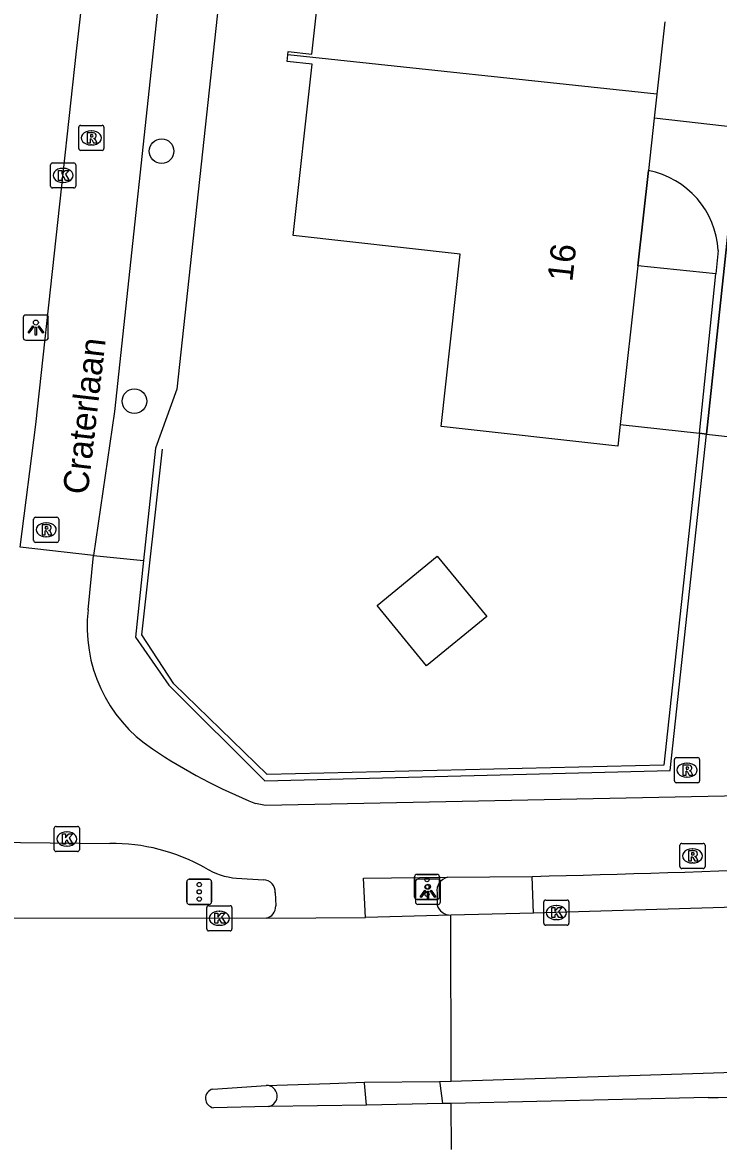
# Model space of a CAD drawing. Extents: x 162398 to 163643, y 386453 to 387397.
# Drawn here: x 162646 to 162673.7, y 386452.93 to 386497.76 of the extents above; entities that cross this region are included whole.
import ezdxf

# ---------------------------------------------------------------- set-up
doc = ezdxf.new("R2010")
doc.units = 0
for name, color, linetype in [('IMGEO_Boom', 7, 'Continuous'), ('IMGEO_Fietspad_gesloten', 7, 'Continuous'), ('IMGEO_Fietspad_open', 7, 'Continuous'), ('IMGEO_Kolk', 7, 'Continuous'), ('IMGEO_Lichtpunt', 7, 'Continuous'), ('IMGEO_Muur', 7, 'Continuous'), ('IMGEO_Openbare_ruimte_label', 7, 'Continuous'), ('IMGEO_Pand', 7, 'Continuous'), ('IMGEO_Pand_nummerreeks', 7, 'Continuous'), ('IMGEO_Pand_overbouw', 7, 'Continuous'), ('IMGEO_Rijbaan_lokaal_open', 7, 'Continuous'), ('IMGEO_Rijbaan_regionaal_gesloten', 7, 'Continuous'), ('IMGEO_Rioolput', 7, 'Continuous'), ('IMGEO_Verkeerseiland_gesloten', 7, 'Continuous'), ('IMGEO_Verkeersregelinstallatiepaal', 7, 'Continuous'), ('IMGEO_Voetpad_open', 7, 'Continuous')]:
    doc.layers.add(name, color=color, linetype=linetype)

msp = doc.modelspace()

# ---------------------------------------------------------------- linework, layer by layer
at = {"layer": 'IMGEO_Boom'}
for centre in [(162651.534, 386492.646), (162650.454, 386482.699)]:
    msp.add_circle(centre, 0.489, dxfattribs=at)
at = {"layer": 'IMGEO_Fietspad_gesloten'}
for points in [[(162648.825, 386476.553), (162645.908, 386476.892)], [(162648.608, 386474.401), (162648.825, 386476.553)], [(162674.593, 386466.997), (162655.671, 386466.609), (162655.276, 386466.693)], [(162624.53, 386465.372), (162649.473, 386465.101)], [(162654.519, 386463.716), (162655.594, 386463.659)], [(162659.652, 386462.15), (162659.567, 386463.727), (162662.92, 386463.76)], [(162662.92, 386463.76), (162666.294, 386463.792)], [(162656.056, 386463.144), (162656.079, 386462.619)], [(162659.696, 386454.688), (162659.613, 386455.559), (162659.609, 386455.599)]]:
    msp.add_lwpolyline(points, dxfattribs=at)
for centre, radius, start, end in [((162654.434, 386473.733), 5.864, 173.4629, 236.1556), ((162663.327, 386486.908), 21.759, 236.0268, 248.2838), ((162649.564, 386457.588), 7.514, 60.4782, 90.6972), ((162642.685, 387395.376), 931.884, 271.451743, 272.779253), ((162654.827, 386466.772), 3.071, 239.4829, 264.2523), ((162655.585, 386463.186), 0.473, 354.8766, 88.9132), ((162655.591, 386462.603), 0.488, 282.1807, 1.8444), ((162655.711, 386455.05), 0.425, 280.0065, 90.9703)]:
    msp.add_arc(centre, radius, start, end, dxfattribs=at)
at = {"layer": 'IMGEO_Fietspad_open'}
for points in [[(162655.899, 386540.406), (162651.56, 386500), (162649.657, 386482.292), (162648.825, 386476.553)], [(162645.908, 386476.892), (162646.532, 386481.777), (162648.149, 386496.622), (162648.531, 386500), (162651.092, 386522.672), (162652.314, 386534.776)]]:
    msp.add_lwpolyline(points, dxfattribs=at)
at = {"layer": 'IMGEO_Kolk'}
for p, q in [((162647.116, 386491.255), (162647.116, 386492.107)), ((162647.191, 386492.181), (162648.043, 386492.181)), ((162647.604, 386491.961), (162647.629, 386491.961)), ((162648.117, 386492.107), (162648.117, 386491.255)), ((162647.627, 386491.401), (162647.602, 386491.401)), ((162648.043, 386491.181), (162647.191, 386491.181)), ((162647.263, 386464.854), (162647.263, 386465.706)), ((162647.338, 386465.78), (162648.19, 386465.78)), ((162647.751, 386465.56), (162647.776, 386465.56)), ((162648.264, 386465.706), (162648.264, 386464.854)), ((162647.774, 386465), (162647.749, 386465)), ((162648.19, 386464.78), (162647.338, 386464.78)), ((162666.75, 386461.925), (162666.75, 386462.777)), ((162666.825, 386462.851), (162667.677, 386462.851)), ((162667.751, 386462.777), (162667.751, 386461.925)), ((162653.334, 386461.699), (162653.334, 386462.551)), ((162653.409, 386462.625), (162654.261, 386462.625)), ((162653.822, 386462.405), (162653.847, 386462.405)), ((162654.335, 386462.551), (162654.335, 386461.699)), ((162667.238, 386462.631), (162667.263, 386462.631)), ((162653.845, 386461.845), (162653.82, 386461.845)), ((162667.677, 386461.851), (162666.825, 386461.851)), ((162667.261, 386462.071), (162667.236, 386462.071)), ((162654.261, 386461.625), (162653.409, 386461.625))]:
    msp.add_line(p, q, dxfattribs=at)
for points in [[(162647.116, 386491.255), (162647.116, 386492.107)], [(162647.191, 386492.181), (162648.043, 386492.181)], [(162647.437, 386491.881), (162647.56, 386491.881), (162647.56, 386491.73), (162647.69, 386491.881), (162647.854, 386491.881), (162647.708, 386491.73), (162647.861, 386491.481), (162647.709, 386491.481), (162647.624, 386491.645), (162647.56, 386491.578), (162647.56, 386491.481), (162647.437, 386491.481), (162647.437, 386491.881)], [(162648.117, 386492.107), (162648.117, 386491.255)], [(162648.043, 386491.181), (162647.191, 386491.181)], [(162647.263, 386464.854), (162647.263, 386465.706)], [(162647.338, 386465.78), (162648.19, 386465.78)], [(162647.584, 386465.48), (162647.707, 386465.48), (162647.707, 386465.329), (162647.837, 386465.48), (162648.001, 386465.48), (162647.855, 386465.329), (162648.008, 386465.08), (162647.856, 386465.08), (162647.771, 386465.244), (162647.707, 386465.177), (162647.707, 386465.08), (162647.584, 386465.08), (162647.584, 386465.48)], [(162648.264, 386465.706), (162648.264, 386464.854)], [(162648.19, 386464.78), (162647.338, 386464.78)], [(162666.75, 386461.925), (162666.75, 386462.777)], [(162666.825, 386462.851), (162667.677, 386462.851)], [(162667.751, 386462.777), (162667.751, 386461.925)], [(162653.334, 386461.699), (162653.334, 386462.551)], [(162653.409, 386462.625), (162654.261, 386462.625)], [(162653.655, 386462.325), (162653.778, 386462.325), (162653.778, 386462.174), (162653.908, 386462.325), (162654.072, 386462.325), (162653.926, 386462.174), (162654.079, 386461.925), (162653.927, 386461.925), (162653.842, 386462.089), (162653.778, 386462.022), (162653.778, 386461.925), (162653.655, 386461.925), (162653.655, 386462.325)], [(162654.335, 386462.551), (162654.335, 386461.699)], [(162667.071, 386462.551), (162667.194, 386462.551), (162667.194, 386462.4), (162667.324, 386462.551), (162667.488, 386462.551), (162667.342, 386462.4), (162667.495, 386462.151), (162667.343, 386462.151), (162667.258, 386462.315), (162667.194, 386462.248), (162667.194, 386462.151), (162667.071, 386462.151), (162667.071, 386462.551)], [(162667.677, 386461.851), (162666.825, 386461.851)], [(162654.261, 386461.625), (162653.409, 386461.625)]]:
    msp.add_lwpolyline(points, dxfattribs=at)
for centre, start, end in [((162647.193, 386492.105), 91.552, 178.448), ((162647.193, 386492.105), 91.552, 178.448), ((162648.041, 386492.105), 1.552, 88.448), ((162648.041, 386492.105), 1.552, 88.448), ((162647.193, 386491.257), 181.552, 268.448), ((162647.193, 386491.257), 181.552, 268.448), ((162648.041, 386491.257), 271.552, 358.448), ((162648.041, 386491.257), 271.552, 358.448), ((162647.34, 386465.704), 91.552, 178.448), ((162647.34, 386465.704), 91.552, 178.448), ((162648.188, 386465.704), 1.552, 88.448), ((162648.188, 386465.704), 1.552, 88.448), ((162647.34, 386464.856), 181.552, 268.448), ((162647.34, 386464.856), 181.552, 268.448), ((162648.188, 386464.856), 271.552, 358.448), ((162648.188, 386464.856), 271.552, 358.448), ((162666.827, 386462.775), 91.552, 178.448), ((162666.827, 386462.775), 91.552, 178.448), ((162667.675, 386462.775), 1.552, 88.448), ((162667.675, 386462.775), 1.552, 88.448), ((162653.411, 386462.549), 91.552, 178.448), ((162653.411, 386462.549), 91.552, 178.448), ((162654.259, 386462.549), 1.552, 88.448), ((162654.259, 386462.549), 1.552, 88.448), ((162666.827, 386461.927), 181.552, 268.448), ((162666.827, 386461.927), 181.552, 268.448), ((162667.675, 386461.927), 271.552, 358.448), ((162667.675, 386461.927), 271.552, 358.448), ((162653.411, 386461.701), 181.552, 268.448), ((162653.411, 386461.701), 181.552, 268.448), ((162654.259, 386461.701), 271.552, 358.448), ((162654.259, 386461.701), 271.552, 358.448)]:
    msp.add_arc(centre, 0.0765, start, end, dxfattribs=at)
for centre, major_axis, ratio, start_param, end_param in [((162647.603, 386491.681), (-0.387, 0.002), 0.722429, 4.712389, 7.853982), ((162647.628, 386491.681), (-0.39, 0.002), 0.717154, 1.570796, 4.712389), ((162647.75, 386465.28), (-0.387, 0.002), 0.722429, 4.712389, 7.853982), ((162647.775, 386465.28), (-0.39, 0.002), 0.717154, 1.570796, 4.712389), ((162653.821, 386462.125), (-0.387, 0.002), 0.722429, 4.712389, 7.853982), ((162653.846, 386462.125), (-0.39, 0.002), 0.717154, 1.570796, 4.712389), ((162667.237, 386462.351), (-0.387, 0.002), 0.722429, 4.712389, 7.853982), ((162667.262, 386462.351), (-0.39, 0.002), 0.717154, 1.570796, 4.712389)]:
    msp.add_ellipse(centre, major_axis=major_axis, ratio=ratio, start_param=start_param, end_param=end_param, dxfattribs=at)
at = {"layer": 'IMGEO_Lichtpunt'}
for p, q in [((162646.03, 386486.031), (162646.03, 386485.224)), ((162646.03, 386486.031), (162646.03, 386485.224)), ((162646.932, 386486.126), (162646.124, 386486.126)), ((162646.932, 386486.126), (162646.124, 386486.126)), ((162647.026, 386485.224), (162647.026, 386486.031)), ((162647.026, 386485.224), (162647.026, 386486.031)), ((162646.124, 386485.13), (162646.932, 386485.13)), ((162646.124, 386485.13), (162646.932, 386485.13)), ((162662.544, 386463.676), (162661.736, 386463.676)), ((162662.544, 386463.676), (162661.736, 386463.676)), ((162661.642, 386463.581), (162661.642, 386462.774)), ((162661.642, 386463.581), (162661.642, 386462.774)), ((162662.638, 386462.774), (162662.638, 386463.581)), ((162662.638, 386462.774), (162662.638, 386463.581)), ((162661.736, 386462.68), (162662.544, 386462.68)), ((162661.736, 386462.68), (162662.544, 386462.68))]:
    msp.add_line(p, q, dxfattribs=at)
for points in [[(162646.404, 386485.695), (162646.443, 386485.667), (162646.255, 386485.405), (162646.217, 386485.432), (162646.404, 386485.695)], [(162646.506, 386485.647), (162646.553, 386485.647), (162646.553, 386485.325), (162646.506, 386485.325), (162646.506, 386485.647)], [(162646.616, 386485.667), (162646.654, 386485.694), (162646.841, 386485.432), (162646.802, 386485.404), (162646.616, 386485.667)], [(162662.016, 386463.245), (162662.055, 386463.217), (162661.867, 386462.955), (162661.829, 386462.982), (162662.016, 386463.245)], [(162662.118, 386463.197), (162662.165, 386463.197), (162662.165, 386462.875), (162662.118, 386462.875), (162662.118, 386463.197)], [(162662.228, 386463.217), (162662.266, 386463.244), (162662.453, 386462.982), (162662.414, 386462.954), (162662.228, 386463.217)]]:
    msp.add_lwpolyline(points, dxfattribs=at)
for centre in [(162646.529, 386485.829), (162662.141, 386463.379)]:
    msp.add_circle(centre, 0.0994, dxfattribs=at)
for centre, start, end in [((162646.124, 386486.031), 90, 180), ((162646.124, 386486.031), 90, 180), ((162646.932, 386486.031), 0, 90), ((162646.932, 386486.031), 0, 90), ((162646.124, 386485.224), 180, 270), ((162646.124, 386485.224), 180, 270), ((162646.932, 386485.224), 270, 0), ((162646.932, 386485.224), 270, 360), ((162661.736, 386463.581), 90, 180), ((162661.736, 386463.581), 90, 180), ((162662.544, 386463.581), 0, 90), ((162662.544, 386463.581), 0, 90), ((162661.736, 386462.774), 180, 270), ((162661.736, 386462.774), 180, 270), ((162662.544, 386462.774), 270, 0), ((162662.544, 386462.774), 270, 360)]:
    msp.add_arc(centre, 0.0946, start, end, dxfattribs=at)
at = {"layer": 'IMGEO_Muur'}
for points in [[(162672.948, 386481.421), (162672.85, 386480.517)], [(162672.85, 386480.517), (162671.524, 386468.223), (162655.736, 386467.848), (162652.022, 386471.451), (162650.749, 386473.407), (162651.57, 386480.789)]]:
    msp.add_lwpolyline(points, dxfattribs=at)
at = {"layer": 'IMGEO_Pand'}
for points in [[(162656.562, 386496.484), (162656.576, 386496.61), (162657.511, 386496.506), (162657.899, 386500), (162658.285, 386503.471), (162664.964, 386502.729), (162665.724, 386509.568)], [(162671.571, 386497.786), (162671.251, 386494.908)], [(162670.493, 386488.084), (162669.791, 386481.774), (162669.695, 386480.909), (162662.664, 386481.69), (162663.427, 386488.55), (162656.767, 386489.29), (162657.524, 386496.103), (162656.532, 386496.213), (162656.562, 386496.484)], [(162671.251, 386494.908), (162656.562, 386496.484)], [(162671.251, 386494.908), (162671.145, 386493.953), (162670.914, 386491.872)], [(162670.493, 386488.084), (162670.914, 386491.872)], [(162662.512, 386476.528), (162664.477, 386474.131), (162662.08, 386472.165), (162660.114, 386474.563), (162662.512, 386476.528)]]:
    msp.add_lwpolyline(points, dxfattribs=at)
at = {"layer": 'IMGEO_Pand_overbouw'}
for points in [[(162674.534, 386493.571), (162671.145, 386493.953), (162670.914, 386491.872), (162670.493, 386488.084), (162669.791, 386481.774), (162672.948, 386481.421), (162673.225, 386481.39)], [(162674.534, 386493.571), (162673.225, 386481.39), (162676.718, 386481), (162678.111, 386493.167)]]:
    msp.add_lwpolyline(points, close=True, dxfattribs=at)
at = {"layer": 'IMGEO_Rijbaan_lokaal_open'}
for points in [[(162673.689, 386488.692), (162673.598, 386487.762)], [(162673.225, 386481.39), (162672.948, 386481.421), (162673.598, 386487.762)], [(162673.225, 386481.39), (162676.718, 386481)]]:
    msp.add_lwpolyline(points, dxfattribs=at)
msp.add_arc((162670.277, 386488.515), 3.417, 2.9638, 79.2548, dxfattribs=at)
at = {"layer": 'IMGEO_Rijbaan_regionaal_gesloten'}
for points in [[(162738.894, 386466.632), (162707.241, 386464.248), (162696.541, 386463.625), (162677.057, 386462.649), (162666.342, 386462.323)], [(162666.342, 386462.323), (162663.044, 386462.248)], [(162655.694, 386462.126), (162624.533, 386462.102)], [(162655.694, 386462.126), (162659.652, 386462.15)], [(162663.044, 386462.248), (162659.652, 386462.15)], [(162663.064, 386455.639), (162663.044, 386462.248)], [(162663.064, 386455.639), (162683.946, 386456.306), (162698.037, 386457.061), (162718.633, 386458.415)], [(162655.704, 386455.475), (162658.249, 386455.556), (162659.609, 386455.599)], [(162659.609, 386455.599), (162662.604, 386455.624)], [(162662.604, 386455.624), (162663.064, 386455.639)], [(162653.577, 386455.329), (162655.704, 386455.475)], [(162655.785, 386454.632), (162653.602, 386454.587)], [(162659.696, 386454.688), (162655.785, 386454.632)], [(162662.716, 386454.749), (162659.696, 386454.688)], [(162663.067, 386454.757), (162662.716, 386454.749)], [(162673.297, 386454.988), (162663.067, 386454.757)], [(162663.073, 386452.927), (162663.067, 386454.757)]]:
    msp.add_lwpolyline(points, dxfattribs=at)
for centre, radius, start, end in [((162653.661, 386454.96), 0.378, 102.8084, 261.0511), ((162664.034, 386819.844), 364.974, 271.45438, 273.40835)]:
    msp.add_arc(centre, radius, start, end, dxfattribs=at)
at = {"layer": 'IMGEO_Rioolput'}
for p, q in [((162648.313, 386493.674), (162649.165, 386493.674)), ((162648.238, 386492.748), (162648.238, 386493.6)), ((162648.726, 386493.454), (162648.751, 386493.454)), ((162649.239, 386493.6), (162649.239, 386492.748)), ((162648.749, 386492.894), (162648.724, 386492.894)), ((162649.165, 386492.674), (162648.313, 386492.674)), ((162646.442, 386477.155), (162646.442, 386478.007)), ((162646.517, 386478.081), (162647.369, 386478.081)), ((162647.443, 386478.007), (162647.443, 386477.155)), ((162646.93, 386477.861), (162646.955, 386477.861)), ((162647.369, 386477.081), (162646.517, 386477.081)), ((162646.953, 386477.301), (162646.928, 386477.301)), ((162671.951, 386467.593), (162671.951, 386468.445)), ((162672.026, 386468.519), (162672.878, 386468.519)), ((162672.439, 386468.299), (162672.464, 386468.299)), ((162672.952, 386468.445), (162672.952, 386467.593)), ((162672.462, 386467.739), (162672.437, 386467.739)), ((162672.878, 386467.519), (162672.026, 386467.519)), ((162672.169, 386464.18), (162672.169, 386465.032)), ((162672.244, 386465.106), (162673.096, 386465.106)), ((162673.17, 386465.032), (162673.17, 386464.18)), ((162672.657, 386464.886), (162672.682, 386464.886)), ((162673.096, 386464.106), (162672.244, 386464.106)), ((162672.68, 386464.326), (162672.655, 386464.326))]:
    msp.add_line(p, q, dxfattribs=at)
for points in [[(162648.313, 386493.674), (162649.165, 386493.674)], [(162648.238, 386492.748), (162648.238, 386493.6)], [(162648.827, 386493.372), (162648.575, 386493.374), (162648.575, 386492.974)], [(162648.753, 386493.293), (162648.699, 386493.293), (162648.699, 386493.212)], [(162648.699, 386493.212), (162648.751, 386493.212)], [(162649.239, 386493.6), (162649.239, 386492.748)], [(162648.575, 386492.974), (162648.699, 386492.974), (162648.699, 386493.136), (162648.71, 386493.136)], [(162648.757, 386493.107), (162648.828, 386492.974), (162648.968, 386492.974), (162648.903, 386493.1)], [(162649.165, 386492.674), (162648.313, 386492.674)], [(162646.442, 386477.155), (162646.442, 386478.007)], [(162646.517, 386478.081), (162647.369, 386478.081)], [(162647.443, 386478.007), (162647.443, 386477.155)], [(162647.031, 386477.779), (162646.779, 386477.781), (162646.779, 386477.381)], [(162646.779, 386477.381), (162646.903, 386477.381), (162646.903, 386477.543), (162646.914, 386477.543)], [(162646.957, 386477.7), (162646.903, 386477.7), (162646.903, 386477.619)], [(162646.903, 386477.619), (162646.955, 386477.619)], [(162646.961, 386477.514), (162647.032, 386477.381), (162647.172, 386477.381), (162647.107, 386477.507)], [(162647.369, 386477.081), (162646.517, 386477.081)], [(162671.951, 386467.593), (162671.951, 386468.445)], [(162672.026, 386468.519), (162672.878, 386468.519)], [(162672.54, 386468.217), (162672.288, 386468.219), (162672.288, 386467.819)], [(162672.466, 386468.138), (162672.412, 386468.138), (162672.412, 386468.057)], [(162672.952, 386468.445), (162672.952, 386467.593)], [(162672.288, 386467.819), (162672.412, 386467.819), (162672.412, 386467.981), (162672.423, 386467.981)], [(162672.412, 386468.057), (162672.464, 386468.057)], [(162672.47, 386467.952), (162672.541, 386467.819), (162672.681, 386467.819), (162672.616, 386467.945)], [(162672.878, 386467.519), (162672.026, 386467.519)], [(162672.169, 386464.18), (162672.169, 386465.032)], [(162672.244, 386465.106), (162673.096, 386465.106)], [(162673.17, 386465.032), (162673.17, 386464.18)], [(162672.758, 386464.804), (162672.506, 386464.806), (162672.506, 386464.406)], [(162672.506, 386464.406), (162672.63, 386464.406), (162672.63, 386464.568), (162672.641, 386464.568)], [(162672.684, 386464.725), (162672.63, 386464.725), (162672.63, 386464.644)], [(162672.63, 386464.644), (162672.682, 386464.644)], [(162672.688, 386464.539), (162672.759, 386464.406), (162672.899, 386464.406), (162672.834, 386464.532)], [(162673.096, 386464.106), (162672.244, 386464.106)]]:
    msp.add_lwpolyline(points, dxfattribs=at)
for centre, radius, start, end in [((162648.315, 386493.598), 0.0765, 91.552, 178.448), ((162648.315, 386493.598), 0.0765, 91.552, 178.448), ((162649.163, 386493.598), 0.0765, 1.552, 88.448), ((162649.163, 386493.598), 0.0765, 1.552, 88.448), ((162648.735, 386493.401), 0.19, 274.7715, 282.9687), ((162648.759, 386493.197), 0.0964, 77.0061, 93.1865), ((162648.773, 386493.254), 0.0378, 276.6634, 79.6772), ((162648.826, 386493.262), 0.109, 350.3612, 89.416), ((162648.824, 386493.262), 0.112, 277.5842, 350.9817), ((162648.315, 386492.75), 0.0765, 181.552, 268.448), ((162648.315, 386492.75), 0.0765, 181.552, 268.448), ((162648.709, 386493.083), 0.0533, 26.0293, 88.6989), ((162648.808, 386493.047), 0.108, 29.5134, 73.7905), ((162649.163, 386492.75), 0.0765, 271.552, 358.448), ((162649.163, 386492.75), 0.0765, 271.552, 358.448), ((162646.519, 386478.005), 0.0765, 91.552, 178.448), ((162646.519, 386478.005), 0.0765, 91.552, 178.448), ((162647.367, 386478.005), 0.0765, 1.552, 88.448), ((162647.367, 386478.005), 0.0765, 1.552, 88.448), ((162646.913, 386477.49), 0.0533, 26.0293, 88.6989), ((162646.939, 386477.808), 0.19, 274.7715, 282.9687), ((162646.963, 386477.604), 0.0964, 77.0061, 93.1865), ((162646.977, 386477.661), 0.0378, 276.6634, 79.6772), ((162647.03, 386477.669), 0.109, 350.3612, 89.416), ((162647.028, 386477.669), 0.112, 277.5842, 350.9817), ((162647.012, 386477.454), 0.108, 29.5134, 73.7905), ((162646.519, 386477.157), 0.0765, 181.552, 268.448), ((162646.519, 386477.157), 0.0765, 181.552, 268.448), ((162647.367, 386477.157), 0.0765, 271.552, 358.448), ((162647.367, 386477.157), 0.0765, 271.552, 358.448), ((162672.028, 386468.443), 0.0765, 91.552, 178.448), ((162672.028, 386468.443), 0.0765, 91.552, 178.448), ((162672.472, 386468.042), 0.0964, 77.0061, 93.1865), ((162672.486, 386468.099), 0.0378, 276.6634, 79.6772), ((162672.539, 386468.107), 0.109, 350.3612, 89.416), ((162672.537, 386468.107), 0.112, 277.5842, 350.9817), ((162672.876, 386468.443), 0.0765, 1.552, 88.448), ((162672.876, 386468.443), 0.0765, 1.552, 88.448), ((162672.422, 386467.928), 0.0533, 26.0293, 88.6989), ((162672.448, 386468.246), 0.19, 274.7715, 282.9687), ((162672.521, 386467.892), 0.108, 29.5134, 73.7905), ((162672.028, 386467.595), 0.0765, 181.552, 268.448), ((162672.028, 386467.595), 0.0765, 181.552, 268.448), ((162672.876, 386467.595), 0.0765, 271.552, 358.448), ((162672.876, 386467.595), 0.0765, 271.552, 358.448), ((162672.246, 386465.03), 0.0765, 91.552, 178.448), ((162672.246, 386465.03), 0.0765, 91.552, 178.448), ((162673.094, 386465.03), 0.0765, 1.552, 88.448), ((162673.094, 386465.03), 0.0765, 1.552, 88.448), ((162672.64, 386464.515), 0.0533, 26.0293, 88.6989), ((162672.666, 386464.833), 0.19, 274.7715, 282.9687), ((162672.69, 386464.629), 0.0964, 77.0061, 93.1865), ((162672.704, 386464.686), 0.0378, 276.6634, 79.6772), ((162672.757, 386464.694), 0.109, 350.3612, 89.416), ((162672.755, 386464.694), 0.112, 277.5842, 350.9817), ((162672.739, 386464.479), 0.108, 29.5134, 73.7905), ((162672.246, 386464.182), 0.0765, 181.552, 268.448), ((162672.246, 386464.182), 0.0765, 181.552, 268.448), ((162673.094, 386464.182), 0.0765, 271.552, 358.448), ((162673.094, 386464.182), 0.0765, 271.552, 358.448)]:
    msp.add_arc(centre, radius, start, end, dxfattribs=at)
for centre, major_axis, ratio, start_param, end_param in [((162648.725, 386493.174), (-0.387, 0.002), 0.722429, 4.712389, 7.853982), ((162648.75, 386493.174), (-0.39, 0.002), 0.717154, 1.570796, 4.712389), ((162646.929, 386477.581), (-0.387, 0.002), 0.722429, 4.712389, 7.853982), ((162646.954, 386477.581), (-0.39, 0.002), 0.717154, 1.570796, 4.712389), ((162672.438, 386468.019), (-0.387, 0.002), 0.722429, 4.712389, 7.853982), ((162672.463, 386468.019), (-0.39, 0.002), 0.717154, 1.570796, 4.712389), ((162672.656, 386464.606), (-0.387, 0.002), 0.722429, 4.712389, 7.853982), ((162672.681, 386464.606), (-0.39, 0.002), 0.717154, 1.570796, 4.712389)]:
    msp.add_ellipse(centre, major_axis=major_axis, ratio=ratio, start_param=start_param, end_param=end_param, dxfattribs=at)
at = {"layer": 'IMGEO_Verkeerseiland_gesloten'}
msp.add_lwpolyline([(162666.342, 386462.323), (162666.294, 386463.792)], dxfattribs=at)
at = {"layer": 'IMGEO_Verkeersregelinstallatiepaal'}
for p, q in [((162652.637, 386463.677), (162653.427, 386463.677)), ((162653.427, 386463.677), (162652.637, 386463.677)), ((162661.605, 386462.971), (162661.605, 386463.771)), ((162661.605, 386463.771), (162661.605, 386462.971)), ((162661.705, 386463.871), (162662.495, 386463.871)), ((162662.495, 386463.871), (162661.705, 386463.871)), ((162662.595, 386463.771), (162662.595, 386462.971)), ((162662.595, 386462.971), (162662.595, 386463.771)), ((162652.537, 386462.777), (162652.537, 386463.577)), ((162652.537, 386463.577), (162652.537, 386462.777)), ((162653.527, 386463.577), (162653.527, 386462.777)), ((162653.527, 386462.777), (162653.527, 386463.577)), ((162662.495, 386462.871), (162661.705, 386462.871)), ((162661.705, 386462.871), (162662.495, 386462.871)), ((162653.427, 386462.677), (162652.637, 386462.677)), ((162652.637, 386462.677), (162653.427, 386462.677))]:
    msp.add_line(p, q, dxfattribs=at)
for centre in [(162662.1, 386463.661), (162653.032, 386463.467), (162653.032, 386463.177), (162662.1, 386463.371), (162662.1, 386463.081), (162653.032, 386462.887)]:
    msp.add_circle(centre, 0.085, dxfattribs=at)
for centre, start, end in [((162652.637, 386463.577), 90, 180), ((162652.637, 386463.577), 90, 180), ((162653.427, 386463.577), 0, 90), ((162653.427, 386463.577), 360, 90), ((162661.705, 386463.771), 90, 180), ((162661.705, 386463.771), 90, 180), ((162662.495, 386463.771), 0, 90), ((162662.495, 386463.771), 360, 90), ((162652.637, 386462.777), 180, 270), ((162652.637, 386462.777), 180, 270), ((162653.427, 386462.777), 270, 0), ((162653.427, 386462.777), 270, 0), ((162661.705, 386462.971), 180, 270), ((162661.705, 386462.971), 180, 270), ((162662.495, 386462.971), 270, 0), ((162662.495, 386462.971), 270, 0)]:
    msp.add_arc(centre, 0.1, start, end, dxfattribs=at)
at = {"layer": 'IMGEO_Voetpad_open'}
for points in [[(162659.642, 386552.743), (162653.954, 386500), (162652.14, 386483.177), (162651.294, 386480.824), (162650.821, 386476.366)], [(162673.598, 386487.762), (162670.493, 386488.084)], [(162650.821, 386476.366), (162650.496, 386473.305), (162651.817, 386471.397), (162655.639, 386467.593), (162671.786, 386468.002), (162673.225, 386481.39)], [(162648.825, 386476.553), (162650.821, 386476.366)], [(162662.5, 386463.135), (162662.501, 386462.65)], [(162662.604, 386455.624), (162662.611, 386455.566), (162662.716, 386454.749)]]:
    msp.add_lwpolyline(points, dxfattribs=at)
for centre, radius, start, end in [((162663.05, 386463.219), 0.556, 103.5188, 188.679), ((162663.058, 386462.835), 0.587, 198.3651, 268.6075)]:
    msp.add_arc(centre, radius, start, end, dxfattribs=at)

# ---------------------------------------------------------------- texts
at = {"layer": 'IMGEO_Openbare_ruimte_label'}
msp.add_text('Craterlaan', height=1, rotation=83.337, dxfattribs=at).set_placement((162648.589, 386478.953))
at = {"layer": 'IMGEO_Pand_nummerreeks'}
msp.add_text('16', height=1, rotation=83.6598, dxfattribs=at).set_placement((162667.884, 386487.425))

doc.saveas('drawing.dxf')
